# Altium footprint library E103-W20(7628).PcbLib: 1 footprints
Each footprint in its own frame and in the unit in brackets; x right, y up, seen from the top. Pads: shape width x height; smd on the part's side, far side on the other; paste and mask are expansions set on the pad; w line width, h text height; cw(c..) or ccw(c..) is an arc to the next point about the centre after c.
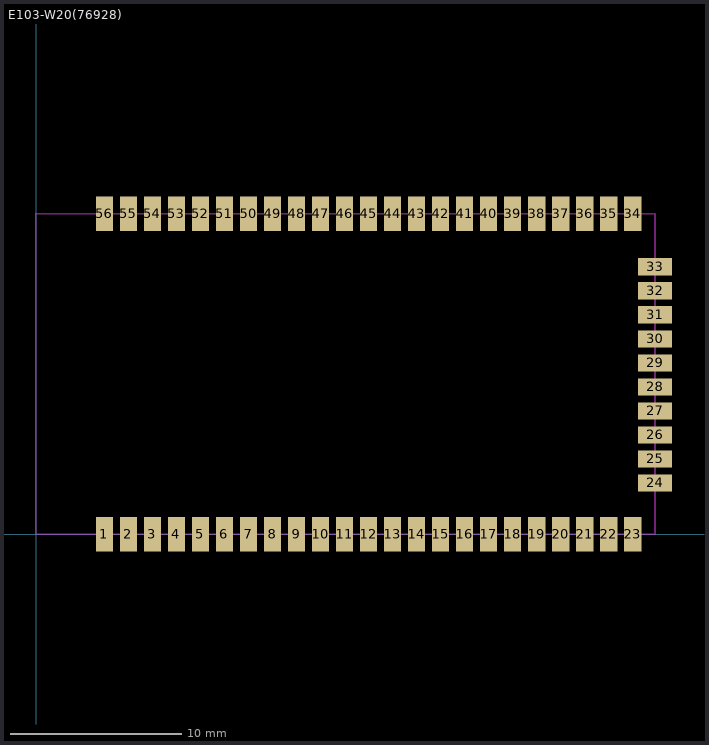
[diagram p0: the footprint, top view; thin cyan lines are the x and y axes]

## E103-W20(76928) [mm]
height 2.5
pads (56):
  rect 1x2 smd: 1(3.989,-0.002) 2(5.389,-0.002) 3(6.789,-0.002) 4(8.189,-0.002) 5(9.589,-0.002) 6(10.989,-0.002) 7(12.389,-0.002) 8(13.789,-0.002) 9(15.189,-0.002) 10(16.589,-0.002) 11(17.989,-0.002) 12(19.389,-0.002) 13(20.789,-0.002) 14(22.189,-0.002) 15(23.589,-0.002) 16(24.989,-0.002) 17(26.389,-0.002) 18(27.789,-0.002) 19(29.189,-0.002) 20(30.589,-0.002) 21(31.989,-0.002) 22(33.389,-0.002) 23(34.789,-0.002) 34(34.789,18.698) 35(33.389,18.698) 36(31.989,18.698) 37(30.589,18.698) 38(29.189,18.698) 39(27.789,18.698) 40(26.389,18.698) 41(24.989,18.698) 42(23.589,18.698) 43(22.189,18.698) 44(20.789,18.698) 45(19.389,18.698) 46(17.989,18.698) 47(16.589,18.698) 48(15.189,18.698) 49(13.789,18.698) 50(12.389,18.698) 51(10.989,18.698) 52(9.589,18.698) 53(8.189,18.698) 54(6.789,18.698) 55(5.389,18.698) 56(3.989,18.698)
  rect 2x1 smd: 24(36.089,2.998) 25(36.089,4.398) 26(36.089,5.798) 27(36.089,7.198) 28(36.089,8.598) 29(36.089,9.998) 30(36.089,11.398) 31(36.089,12.798) 32(36.089,14.198) 33(36.089,15.598)
Keep-Out Layer:
  lines w0.1: -0.011,18.698 36.089,18.698 36.089,-0.002 ; -0.011,18.7 -0.011,0 36.089,0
